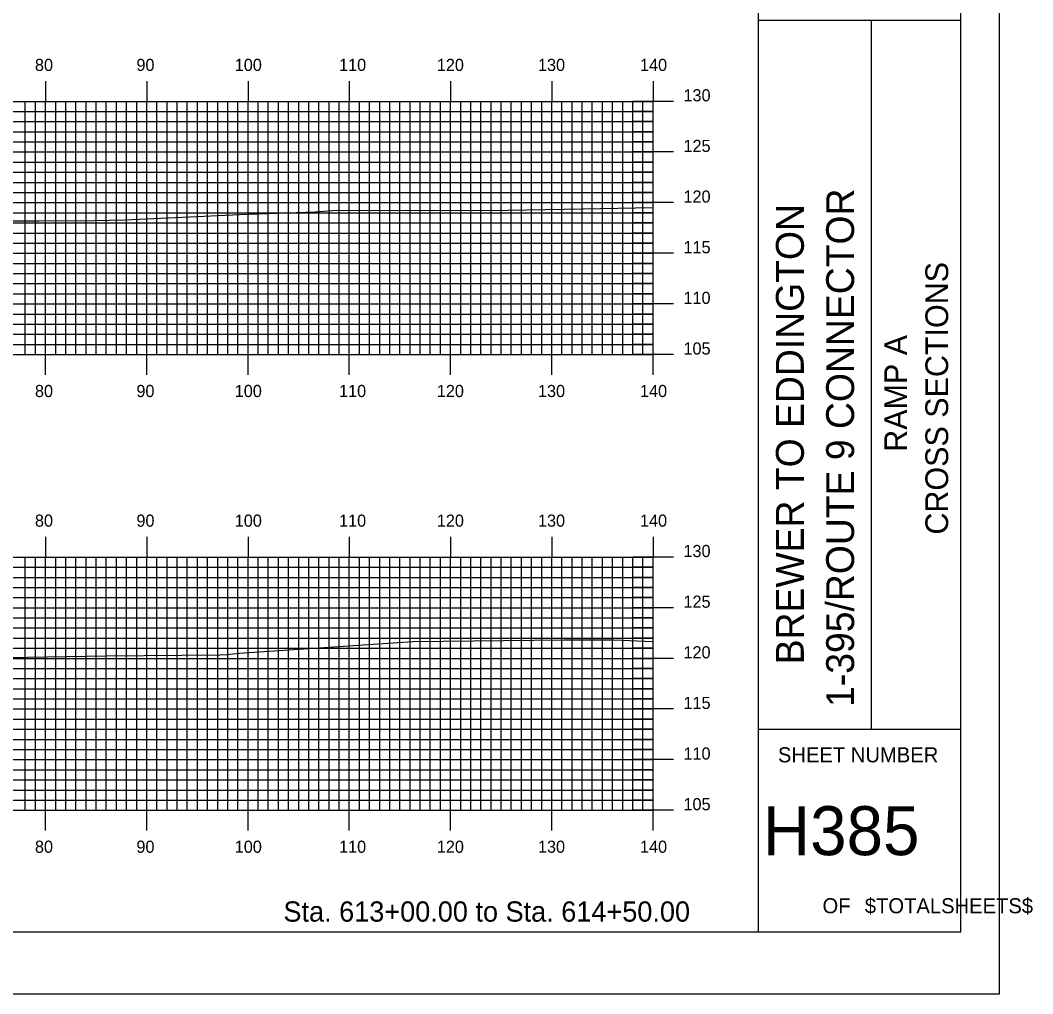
# Model space of a CAD drawing. Extents: x 844143 to 844486, y 363538 to 363758.
# Drawn here: x 844386 to 844485.9, y 363537.6 to 363633.7 of the extents above; entities that cross this region are included whole.
import ezdxf

# ---------------------------------------------------------------- set-up
doc = ezdxf.new("R2010")
doc.units = 0
for name, color, linetype in [('BORDER', 7, 'Continuous'), ('H_V ANNOTATION', 7, 'Continuous'), ('MAJOR', 7, 'Continuous'), ('MINOR', 7, 'Continuous'), ('PLOT BOUNDARY', 7, 'Continuous'), ('S_Roadway_Centerline', 7, 'Continuous')]:
    doc.layers.add(name, color=color, linetype=linetype)

msp = doc.modelspace()

# ---------------------------------------------------------------- linework, layer by layer
at = {"layer": 'BORDER'}
for p, q in [((844458.85, 363543.721), (844458.85, 363753.721)), ((844458.85, 363633.727), (844478.85, 363633.727)), ((844470.033, 363563.727), (844470.033, 363633.727)), ((844458.85, 363563.727), (844478.85, 363563.727))]:
    msp.add_line(p, q, dxfattribs=at)
msp.add_lwpolyline([(844158.85, 363543.721), (844478.85, 363543.721), (844478.85, 363753.721), (844158.85, 363753.721)], close=True, dxfattribs=at)
at = {"layer": 'MAJOR'}
for p, q in [((844388.45, 363627.725), (844388.45, 363625.721)), ((844398.45, 363627.725), (844398.45, 363625.721)), ((844408.45, 363627.725), (844408.45, 363625.721)), ((844418.45, 363627.725), (844418.45, 363625.721)), ((844428.45, 363627.725), (844428.45, 363625.721)), ((844438.45, 363627.725), (844438.45, 363625.721)), ((844448.45, 363627.725), (844448.45, 363625.721)), ((844168.45, 363625.721), (844448.45, 363625.721)), ((844168.45, 363625.721), (844448.45, 363625.721)), ((844388.45, 363600.721), (844388.45, 363625.721)), ((844398.45, 363600.721), (844398.45, 363625.721)), ((844408.45, 363600.721), (844408.45, 363625.721)), ((844418.45, 363600.721), (844418.45, 363625.721)), ((844428.45, 363600.721), (844428.45, 363625.721)), ((844438.45, 363600.721), (844438.45, 363625.721)), ((844450.454, 363625.721), (844446.446, 363625.721)), ((844448.45, 363600.721), (844448.45, 363625.721)), ((844448.45, 363600.721), (844448.45, 363625.721)), ((844168.45, 363620.721), (844448.45, 363620.721)), ((844450.454, 363620.721), (844446.446, 363620.721)), ((844168.45, 363615.721), (844448.45, 363615.721)), ((844450.454, 363615.721), (844446.446, 363615.721)), ((844168.45, 363610.721), (844448.45, 363610.721)), ((844450.454, 363610.721), (844446.446, 363610.721)), ((844168.45, 363605.721), (844448.45, 363605.721)), ((844450.454, 363605.721), (844446.446, 363605.721)), ((844168.45, 363600.721), (844448.45, 363600.721)), ((844168.45, 363600.721), (844448.45, 363600.721)), ((844388.45, 363598.717), (844388.45, 363600.721)), ((844398.45, 363598.717), (844398.45, 363600.721)), ((844408.45, 363598.717), (844408.45, 363600.721)), ((844418.45, 363598.717), (844418.45, 363600.721)), ((844428.45, 363598.717), (844428.45, 363600.721)), ((844438.45, 363598.717), (844438.45, 363600.721)), ((844450.454, 363600.721), (844446.446, 363600.721)), ((844448.45, 363598.717), (844448.45, 363600.721)), ((844388.45, 363582.725), (844388.45, 363580.721)), ((844398.45, 363582.725), (844398.45, 363580.721)), ((844408.45, 363582.725), (844408.45, 363580.721)), ((844418.45, 363582.725), (844418.45, 363580.721)), ((844428.45, 363582.725), (844428.45, 363580.721)), ((844438.45, 363582.725), (844438.45, 363580.721)), ((844448.45, 363582.725), (844448.45, 363580.721)), ((844168.45, 363580.721), (844448.45, 363580.721)), ((844168.45, 363580.721), (844448.45, 363580.721)), ((844388.45, 363555.721), (844388.45, 363580.721)), ((844398.45, 363555.721), (844398.45, 363580.721)), ((844408.45, 363555.721), (844408.45, 363580.721)), ((844418.45, 363555.721), (844418.45, 363580.721)), ((844428.45, 363555.721), (844428.45, 363580.721)), ((844438.45, 363555.721), (844438.45, 363580.721)), ((844450.454, 363580.721), (844446.446, 363580.721)), ((844448.45, 363555.721), (844448.45, 363580.721)), ((844448.45, 363555.721), (844448.45, 363580.721)), ((844168.45, 363575.721), (844448.45, 363575.721)), ((844450.454, 363575.721), (844446.446, 363575.721)), ((844168.45, 363570.721), (844448.45, 363570.721)), ((844450.454, 363570.721), (844446.446, 363570.721)), ((844168.45, 363565.721), (844448.45, 363565.721)), ((844450.454, 363565.721), (844446.446, 363565.721)), ((844168.45, 363560.721), (844448.45, 363560.721)), ((844450.454, 363560.721), (844446.446, 363560.721)), ((844168.45, 363555.721), (844448.45, 363555.721)), ((844168.45, 363555.721), (844448.45, 363555.721)), ((844388.45, 363553.717), (844388.45, 363555.721)), ((844398.45, 363553.717), (844398.45, 363555.721)), ((844408.45, 363553.717), (844408.45, 363555.721)), ((844418.45, 363553.717), (844418.45, 363555.721)), ((844428.45, 363553.717), (844428.45, 363555.721)), ((844438.45, 363553.717), (844438.45, 363555.721)), ((844450.454, 363555.721), (844446.446, 363555.721)), ((844448.45, 363553.717), (844448.45, 363555.721))]:
    msp.add_line(p, q, dxfattribs=at)
at = {"layer": 'MINOR'}
for p, q in [((844386.45, 363600.721), (844386.45, 363625.721)), ((844387.45, 363600.721), (844387.45, 363625.721)), ((844389.45, 363600.721), (844389.45, 363625.721)), ((844390.45, 363600.721), (844390.45, 363625.721)), ((844391.45, 363600.721), (844391.45, 363625.721)), ((844392.45, 363600.721), (844392.45, 363625.721)), ((844393.45, 363600.721), (844393.45, 363625.721)), ((844394.45, 363600.721), (844394.45, 363625.721)), ((844395.45, 363600.721), (844395.45, 363625.721)), ((844396.45, 363600.721), (844396.45, 363625.721)), ((844397.45, 363600.721), (844397.45, 363625.721)), ((844399.45, 363600.721), (844399.45, 363625.721)), ((844400.45, 363600.721), (844400.45, 363625.721)), ((844401.45, 363600.721), (844401.45, 363625.721)), ((844402.45, 363600.721), (844402.45, 363625.721)), ((844403.45, 363600.721), (844403.45, 363625.721)), ((844404.45, 363600.721), (844404.45, 363625.721)), ((844405.45, 363600.721), (844405.45, 363625.721)), ((844406.45, 363600.721), (844406.45, 363625.721)), ((844407.45, 363600.721), (844407.45, 363625.721)), ((844409.45, 363600.721), (844409.45, 363625.721)), ((844410.45, 363600.721), (844410.45, 363625.721)), ((844411.45, 363600.721), (844411.45, 363625.721)), ((844412.45, 363600.721), (844412.45, 363625.721)), ((844413.45, 363600.721), (844413.45, 363625.721)), ((844414.45, 363600.721), (844414.45, 363625.721)), ((844415.45, 363600.721), (844415.45, 363625.721)), ((844416.45, 363600.721), (844416.45, 363625.721)), ((844417.45, 363600.721), (844417.45, 363625.721)), ((844419.45, 363600.721), (844419.45, 363625.721)), ((844420.45, 363600.721), (844420.45, 363625.721)), ((844421.45, 363600.721), (844421.45, 363625.721)), ((844422.45, 363600.721), (844422.45, 363625.721)), ((844423.45, 363600.721), (844423.45, 363625.721)), ((844424.45, 363600.721), (844424.45, 363625.721)), ((844425.45, 363600.721), (844425.45, 363625.721)), ((844426.45, 363600.721), (844426.45, 363625.721)), ((844427.45, 363600.721), (844427.45, 363625.721)), ((844429.45, 363600.721), (844429.45, 363625.721)), ((844430.45, 363600.721), (844430.45, 363625.721)), ((844431.45, 363600.721), (844431.45, 363625.721)), ((844432.45, 363600.721), (844432.45, 363625.721)), ((844433.45, 363600.721), (844433.45, 363625.721)), ((844434.45, 363600.721), (844434.45, 363625.721)), ((844435.45, 363600.721), (844435.45, 363625.721)), ((844436.45, 363600.721), (844436.45, 363625.721)), ((844437.45, 363600.721), (844437.45, 363625.721)), ((844439.45, 363600.721), (844439.45, 363625.721)), ((844440.45, 363600.721), (844440.45, 363625.721)), ((844441.45, 363600.721), (844441.45, 363625.721)), ((844442.45, 363600.721), (844442.45, 363625.721)), ((844443.45, 363600.721), (844443.45, 363625.721)), ((844444.45, 363600.721), (844444.45, 363625.721)), ((844445.45, 363600.721), (844445.45, 363625.721)), ((844446.45, 363600.721), (844446.45, 363625.721)), ((844447.45, 363600.721), (844447.45, 363625.721)), ((844168.45, 363624.721), (844448.45, 363624.721)), ((844448.45, 363624.721), (844446.446, 363624.721)), ((844168.45, 363623.721), (844448.45, 363623.721)), ((844448.45, 363623.721), (844446.446, 363623.721)), ((844168.45, 363622.721), (844448.45, 363622.721)), ((844448.45, 363622.721), (844446.446, 363622.721)), ((844168.45, 363621.721), (844448.45, 363621.721)), ((844448.45, 363621.721), (844446.446, 363621.721)), ((844168.45, 363619.721), (844448.45, 363619.721)), ((844448.45, 363619.721), (844446.446, 363619.721)), ((844168.45, 363618.721), (844448.45, 363618.721)), ((844448.45, 363618.721), (844446.446, 363618.721)), ((844168.45, 363617.721), (844448.45, 363617.721)), ((844448.45, 363617.721), (844446.446, 363617.721)), ((844168.45, 363616.721), (844448.45, 363616.721)), ((844448.45, 363616.721), (844446.446, 363616.721)), ((844168.45, 363614.721), (844448.45, 363614.721)), ((844448.45, 363614.721), (844446.446, 363614.721)), ((844168.45, 363613.721), (844448.45, 363613.721)), ((844448.45, 363613.721), (844446.446, 363613.721)), ((844168.45, 363612.721), (844448.45, 363612.721)), ((844448.45, 363612.721), (844446.446, 363612.721)), ((844168.45, 363611.721), (844448.45, 363611.721)), ((844448.45, 363611.721), (844446.446, 363611.721)), ((844168.45, 363609.721), (844448.45, 363609.721)), ((844448.45, 363609.721), (844446.446, 363609.721)), ((844168.45, 363608.721), (844448.45, 363608.721)), ((844448.45, 363608.721), (844446.446, 363608.721)), ((844168.45, 363607.721), (844448.45, 363607.721)), ((844448.45, 363607.721), (844446.446, 363607.721)), ((844168.45, 363606.721), (844448.45, 363606.721)), ((844448.45, 363606.721), (844446.446, 363606.721)), ((844168.45, 363604.721), (844448.45, 363604.721)), ((844448.45, 363604.721), (844446.446, 363604.721)), ((844168.45, 363603.721), (844448.45, 363603.721)), ((844448.45, 363603.721), (844446.446, 363603.721)), ((844168.45, 363602.721), (844448.45, 363602.721)), ((844448.45, 363602.721), (844446.446, 363602.721)), ((844168.45, 363601.721), (844448.45, 363601.721)), ((844448.45, 363601.721), (844446.446, 363601.721)), ((844386.45, 363555.721), (844386.45, 363580.721)), ((844387.45, 363555.721), (844387.45, 363580.721)), ((844389.45, 363555.721), (844389.45, 363580.721)), ((844390.45, 363555.721), (844390.45, 363580.721)), ((844391.45, 363555.721), (844391.45, 363580.721)), ((844392.45, 363555.721), (844392.45, 363580.721)), ((844393.45, 363555.721), (844393.45, 363580.721)), ((844394.45, 363555.721), (844394.45, 363580.721)), ((844395.45, 363555.721), (844395.45, 363580.721)), ((844396.45, 363555.721), (844396.45, 363580.721)), ((844397.45, 363555.721), (844397.45, 363580.721)), ((844399.45, 363555.721), (844399.45, 363580.721)), ((844400.45, 363555.721), (844400.45, 363580.721)), ((844401.45, 363555.721), (844401.45, 363580.721)), ((844402.45, 363555.721), (844402.45, 363580.721)), ((844403.45, 363555.721), (844403.45, 363580.721)), ((844404.45, 363555.721), (844404.45, 363580.721)), ((844405.45, 363555.721), (844405.45, 363580.721)), ((844406.45, 363555.721), (844406.45, 363580.721)), ((844407.45, 363555.721), (844407.45, 363580.721)), ((844409.45, 363555.721), (844409.45, 363580.721)), ((844410.45, 363555.721), (844410.45, 363580.721)), ((844411.45, 363555.721), (844411.45, 363580.721)), ((844412.45, 363555.721), (844412.45, 363580.721)), ((844413.45, 363555.721), (844413.45, 363580.721)), ((844414.45, 363555.721), (844414.45, 363580.721)), ((844415.45, 363555.721), (844415.45, 363580.721)), ((844416.45, 363555.721), (844416.45, 363580.721)), ((844417.45, 363555.721), (844417.45, 363580.721)), ((844419.45, 363555.721), (844419.45, 363580.721)), ((844420.45, 363555.721), (844420.45, 363580.721)), ((844421.45, 363555.721), (844421.45, 363580.721)), ((844422.45, 363555.721), (844422.45, 363580.721)), ((844423.45, 363555.721), (844423.45, 363580.721)), ((844424.45, 363555.721), (844424.45, 363580.721)), ((844425.45, 363555.721), (844425.45, 363580.721)), ((844426.45, 363555.721), (844426.45, 363580.721)), ((844427.45, 363555.721), (844427.45, 363580.721)), ((844429.45, 363555.721), (844429.45, 363580.721)), ((844430.45, 363555.721), (844430.45, 363580.721)), ((844431.45, 363555.721), (844431.45, 363580.721)), ((844432.45, 363555.721), (844432.45, 363580.721)), ((844433.45, 363555.721), (844433.45, 363580.721)), ((844434.45, 363555.721), (844434.45, 363580.721)), ((844435.45, 363555.721), (844435.45, 363580.721)), ((844436.45, 363555.721), (844436.45, 363580.721)), ((844437.45, 363555.721), (844437.45, 363580.721)), ((844439.45, 363555.721), (844439.45, 363580.721)), ((844440.45, 363555.721), (844440.45, 363580.721)), ((844441.45, 363555.721), (844441.45, 363580.721)), ((844442.45, 363555.721), (844442.45, 363580.721)), ((844443.45, 363555.721), (844443.45, 363580.721)), ((844444.45, 363555.721), (844444.45, 363580.721)), ((844445.45, 363555.721), (844445.45, 363580.721)), ((844446.45, 363555.721), (844446.45, 363580.721)), ((844447.45, 363555.721), (844447.45, 363580.721)), ((844168.45, 363579.721), (844448.45, 363579.721)), ((844448.45, 363579.721), (844446.446, 363579.721)), ((844168.45, 363578.721), (844448.45, 363578.721)), ((844448.45, 363578.721), (844446.446, 363578.721)), ((844168.45, 363577.721), (844448.45, 363577.721)), ((844448.45, 363577.721), (844446.446, 363577.721)), ((844168.45, 363576.721), (844448.45, 363576.721)), ((844448.45, 363576.721), (844446.446, 363576.721)), ((844168.45, 363574.721), (844448.45, 363574.721)), ((844448.45, 363574.721), (844446.446, 363574.721)), ((844168.45, 363573.721), (844448.45, 363573.721)), ((844448.45, 363573.721), (844446.446, 363573.721)), ((844168.45, 363572.721), (844448.45, 363572.721)), ((844448.45, 363572.721), (844446.446, 363572.721)), ((844168.45, 363571.721), (844448.45, 363571.721)), ((844448.45, 363571.721), (844446.446, 363571.721)), ((844168.45, 363569.721), (844448.45, 363569.721)), ((844448.45, 363569.721), (844446.446, 363569.721)), ((844168.45, 363568.721), (844448.45, 363568.721)), ((844448.45, 363568.721), (844446.446, 363568.721)), ((844168.45, 363567.721), (844448.45, 363567.721)), ((844448.45, 363567.721), (844446.446, 363567.721)), ((844168.45, 363566.721), (844448.45, 363566.721)), ((844448.45, 363566.721), (844446.446, 363566.721)), ((844168.45, 363564.721), (844448.45, 363564.721)), ((844448.45, 363564.721), (844446.446, 363564.721)), ((844168.45, 363563.721), (844448.45, 363563.721)), ((844448.45, 363563.721), (844446.446, 363563.721)), ((844168.45, 363562.721), (844448.45, 363562.721)), ((844448.45, 363562.721), (844446.446, 363562.721)), ((844168.45, 363561.721), (844448.45, 363561.721)), ((844448.45, 363561.721), (844446.446, 363561.721)), ((844168.45, 363559.721), (844448.45, 363559.721)), ((844448.45, 363559.721), (844446.446, 363559.721)), ((844168.45, 363558.721), (844448.45, 363558.721)), ((844448.45, 363558.721), (844446.446, 363558.721)), ((844168.45, 363557.721), (844448.45, 363557.721)), ((844448.45, 363557.721), (844446.446, 363557.721)), ((844168.45, 363556.721), (844448.45, 363556.721)), ((844448.45, 363556.721), (844446.446, 363556.721))]:
    msp.add_line(p, q, dxfattribs=at)
at = {"layer": 'PLOT BOUNDARY'}
msp.add_lwpolyline([(844142.664, 363537.603), (844482.664, 363537.603), (844482.664, 363757.603), (844142.664, 363757.603)], close=True, dxfattribs=at)
at = {"layer": 'S_Roadway_Centerline'}
for points in [[(844381.112, 363613.913), (844387.785, 363613.939), (844393.224, 363613.965), (844396.305, 363614.02), (844407.616, 363614.534), (844415.074, 363614.818), (844417.198, 363614.964), (844420.972, 363614.935), (844434.14, 363614.97), (844441.5, 363615.114), (844448.45, 363615.235)], [(844382.329, 363570.725), (844386.68, 363570.832), (844394.435, 363570.972), (844405.654, 363571.085), (844406.366, 363571.105), (844407.617, 363571.217), (844424.709, 363572.4), (844439.678, 363572.534), (844444.539, 363572.536), (844448.45, 363572.395)]]:
    msp.add_lwpolyline(points, dxfattribs=at)

# ---------------------------------------------------------------- texts
at = {"layer": 'BORDER'}
for s, height, p in [('1-395/ROUTE 9 CONNECTOR', 2.75575, (844468.3, 363565.921)), ('BREWER TO EDDINGTON', 2.75575, (844463.339, 363570.13)), ('CROSS SECTIONS', 2.25, (844477.592, 363582.943)), ('RAMP A', 2.25, (844473.542, 363591.118))]:
    msp.add_text(s, height=height, rotation=90, dxfattribs=at).set_placement(p)
for s, height, p in [('SHEET NUMBER', 1.49054, (844460.781, 363560.454)), ('H385', 4.8388, (844459.29, 363551.286)), ('OF', 1.4905, (844465.184, 363545.547)), ('$TOTALSHEETS$', 1.49054, (844469.363, 363545.547))]:
    msp.add_text(s, height=height, dxfattribs=at).set_placement(p)
at = {"layer": 'H_V ANNOTATION'}
for s, height, p in [('80', 1.2, (844387.401, 363628.721)), ('90', 1.2, (844397.423, 363628.721)), ('100', 1.2, (844407.134, 363628.721)), ('110', 1.2, (844417.434, 363628.721)), ('120', 1.2, (844427.091, 363628.721)), ('130', 1.2, (844437.08, 363628.721)), ('140', 1.2, (844447.155, 363628.721)), ('130', 1.2, (844451.45, 363625.721)), ('125', 1.2, (844451.45, 363620.721)), ('120', 1.2, (844451.45, 363615.721)), ('115', 1.2, (844451.45, 363610.721)), ('110', 1.2, (844451.45, 363605.721)), ('105', 1.2, (844451.45, 363600.721)), ('80', 1.2, (844387.401, 363596.521)), ('90', 1.2, (844397.423, 363596.521)), ('100', 1.2, (844407.134, 363596.521)), ('110', 1.2, (844417.434, 363596.521)), ('120', 1.2, (844427.091, 363596.521)), ('130', 1.2, (844437.08, 363596.521)), ('140', 1.2, (844447.155, 363596.521)), ('80', 1.2, (844387.401, 363583.721)), ('90', 1.2, (844397.423, 363583.721)), ('100', 1.2, (844407.134, 363583.721)), ('110', 1.2, (844417.434, 363583.721)), ('120', 1.2, (844427.091, 363583.721)), ('130', 1.2, (844437.08, 363583.721)), ('140', 1.2, (844447.155, 363583.721)), ('130', 1.2, (844451.45, 363580.721)), ('125', 1.2, (844451.45, 363575.721)), ('120', 1.2, (844451.45, 363570.721)), ('115', 1.2, (844451.45, 363565.721)), ('110', 1.2, (844451.45, 363560.721)), ('105', 1.2, (844451.45, 363555.721)), ('80', 1.2, (844387.401, 363551.521)), ('90', 1.2, (844397.423, 363551.521)), ('100', 1.2, (844407.134, 363551.521)), ('110', 1.2, (844417.434, 363551.521)), ('120', 1.2, (844427.091, 363551.521)), ('130', 1.2, (844437.08, 363551.521)), ('140', 1.2, (844447.155, 363551.521)), ('Sta. 613+00.00 to Sta. 614+50.00', 2.0004, (844411.942, 363544.721))]:
    msp.add_text(s, height=height, dxfattribs=at).set_placement(p)

doc.saveas('drawing.dxf')
